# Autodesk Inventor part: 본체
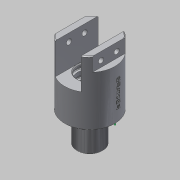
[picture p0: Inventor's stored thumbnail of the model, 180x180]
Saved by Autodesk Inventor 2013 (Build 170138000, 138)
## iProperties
Created: 2019-02
Part Number: 본체
Material: 알루미늄 6061
Document SubType Name: Modeling
Designer: Gpr
Density: 1 g/cm^3
Author: Gpr
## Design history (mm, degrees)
sketch "스케치1"
  geometry: C1 r 29 at (0, 0)
  constraints: 1 centre point
  dimensions: "d0" = 58 diameter of C1
extrude "돌출1" new body sketch "스케치1" distance "d1" = 74; taper "d2" = 0 deg
chamfer "모따기1" distance "d3" = 1; stored, may be unused: second distance "d4" = 2, angle "d5" = 45 deg
sketch "스케치2"
  geometry: C1 r 28 at (0, 0) reference; C2 r 13 at (0, 0)
  constraints: 1 centre point, 1 coincident
  dimensions: "d6" = 26 diameter of C2
extrude "돌출2" join sketch "스케치2" distance "d7" = 5; taper "d8" = 0 deg
sketch "스케치3"
  geometry: C1 r 13 at (0, 0) reference; C2 r 15 at (0, 0)
  constraints: 1 centre point, 1 coincident
  dimensions: "d9" = 30 diameter of C2
extrude "돌출3" join sketch "스케치3" distance "d10" = 29; taper "d11" = 0 deg
chamfer "모따기2" distance "d12" = 1; stored, may be unused: second distance "d13" = 2, angle "d14" = 45 deg
feature "스레드1" dims "d15" = 10, "d16" = 0
sketch "스케치4"
  geometry: L1 (-15, 29)-(15, 29); L2 (22, 29)-(22, -29); L3 (15, -29)-(-15, -29); L4 (-22, -29)-(-22, 29); L5 (15, -29)-(-15, -29); L6 (-15, -29)-(-15, 29); L7 (-15, 29)-(15, 29); L8 (15, 29)-(15, -29); L9 (22, -29)-(31.478, -29); L10 (31.478, -29)-(31.478, 29); L11 (31.478, 29)-(22, 29); L12 (22, 29)-(22, -29); L13 (-22, -29)-(-30.095, -29); L14 (-30.095, -29)-(-30.095, 29); L15 (-30.095, 29)-(-22, 29); L16 (-22, 29)-(-22, -29); 1 further point
  constraints: 32 end point, 8 parallel, 4 horizontal, 4 perpendicular, 2 midpoint
  dimensions: "d17" = 44 distance of L2.end L4.start; "d18" = 58 distance of L2.start L2.end; "d19" = 30 distance of L1.end L1.start; "d20" = 58 distance of L3.end L1.start
extrude "돌출4" cut sketch "스케치4" distance "d21" = 16; taper "d22" = 0 deg
extrude "돌출5" cut sketch "스케치4" distance "d23" = 36; taper "d24" = 0 deg
sketch "스케치5"
  geometry: L1 (0, 0)-(0, 34.641) reference; L2 (0, 0)-(9, 0); L3 (0, 0)-(9, 0); L4 (0, 17.321)-(0, 8.321); L5 (0, 17.321)-(9, 17.321); C1 r 1.322 at (9, 8.321); C2 r 2.014 at (9, 17.321); C3 r 1.322 at (9, 26.321); 1 further point
  constraints: 8 end point, 3 centre point, 2 equal length, 2 horizontal, 2 perpendicular, 1 coincident, 1 midpoint, 1 symmetric about line, 1 other
  dimensions: "d25" = 9 distance of L1.start L2.end; "d26" = 0 distance between parallel lines of L2 L3 (derived); "d27" = 9 distance of L4.start L4.end; "d28" = 90 deg angle of L4 L5 (derived)
hole "구멍1" sketch "스케치5" at (9, 26.321), (9, 8.321) diameter "d29" = 6; stored, may be unused: countersink angle "d33" = 90 deg, drill point angle "d35" = 0 deg; dims "d30" = 6, "d31" = 4, "d32" = 2, "d34" = 8
hole "구멍2" diameter "d38" = 28; stored, may be unused: countersink angle "d42" = 90 deg, drill point angle "d44" = 0 deg; dims "d39" = 6, "d40" = 28, "d41" = 2.65, "d43" = 2.65, "d80" = 10, "d81" = 10
hole "구멍3" diameter "d49" = 28; stored, may be unused: countersink angle "d53" = 90 deg, drill point angle "d55" = 0 deg; dims "d47" = 10, "d48" = 10, "d50" = 6, "d51" = 34, "d52" = 4.7, "d54" = 9
chamfer "모따기3" distance "d56" = 1; stored, may be unused: second distance "d57" = 2, angle "d58" = 45 deg
fillet "모깎기1" dims "d59" = 0.8
hole "구멍4" diameter "d62" = 28; stored, may be unused: countersink angle "d66" = 90 deg, drill point angle "d68" = 0 deg; dims "d63" = 6, "d64" = 34, "d65" = 4.7, "d67" = 8.35, "d82" = 10, "d83" = 10
fillet "모깎기2" dims "d69" = 0.8
hole "구멍5" diameter "d72" = 32; stored, may be unused: countersink angle "d76" = 90 deg, drill point angle "d78" = 0 deg; dims "d70" = 10, "d71" = 10, "d73" = 6, "d74" = 34, "d75" = 4.7, "d77" = 7
hole "구멍6" diameter "d86" = 8; stored, may be unused: countersink angle "d90" = 90 deg, drill point angle "d92" = 0 deg; dims "d84" = 10, "d85" = 10, "d87" = 6, "d88" = 34, "d89" = 4.7, "d91" = 23
chamfer "모따기4" distance "d93" = 1; stored, may be unused: second distance "d94" = 2, angle "d95" = 45 deg
chamfer "모따기5" distance "d105" = 1; stored, may be unused: second distance "d106" = 2, angle "d107" = 45 deg
node "작업 평면2"
sketch "스케치7"
  geometry: 2 further points
  constraints: 1 other
sketch "스케치8"
  geometry: 1 further point
feature "엠보싱1" dims "d108" = 0.5, "d109" = 0
hole "구멍8" diameter "d112" = 12.376; stored, may be unused: countersink angle "d116" = 90 deg, drill point angle "d118" = 118 deg; dims "d110" = 10, "d111" = 10, "d113" = 18, "d114" = 4, "d115" = 2, "d117" = 22
node "솔리드1"
